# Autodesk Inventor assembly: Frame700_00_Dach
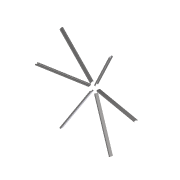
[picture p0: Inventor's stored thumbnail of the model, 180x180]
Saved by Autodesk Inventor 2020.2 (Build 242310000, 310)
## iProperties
_FrameDoc: Frame Assembly
_Version: 15.0.0
Manager: www.cadconsulting.pl
Company: Fabian Stasiak CAD Consulting
Created: 2017-03
Part Number: Frame700_00_Dach
Document SubType Name: Assembly
Designer: F.Stasiak
Catalog Web Link: www.expertbooks.pl
Author: F.Stasiak
Subject: Zbiór ćwiczeń. Autodesk Inventor 2020. Kurs Professional
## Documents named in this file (4)
- C:\2020_Kurs_Professional\R4 MES\Dach\700_00_Dach\Frame\Frame700_00_Dach.iam
- C:\2020_Kurs_Professional\R4 MES\Dach\700_00_Dach\Frame\Skeleton700_00_Dach.ipt
- C:\2020_Kurs_Professional\R4 MES\Dach\700_00_Dach\Frame\ISO CH 140 x 15 00000001.ipt
- ISO CH 140 x 15 00000001.ipt
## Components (7 placed, 2 different names)
1. Model odniesienia ramy
2. ISO CH 140 x 15 00000001:1
3. ISO CH 140 x 15 00000001:2
4. ISO CH 140 x 15 00000001:3
5. ISO CH 140 x 15 00000001:4
6. ISO CH 140 x 15 00000001:5
7. ISO CH 140 x 15 00000001:6
